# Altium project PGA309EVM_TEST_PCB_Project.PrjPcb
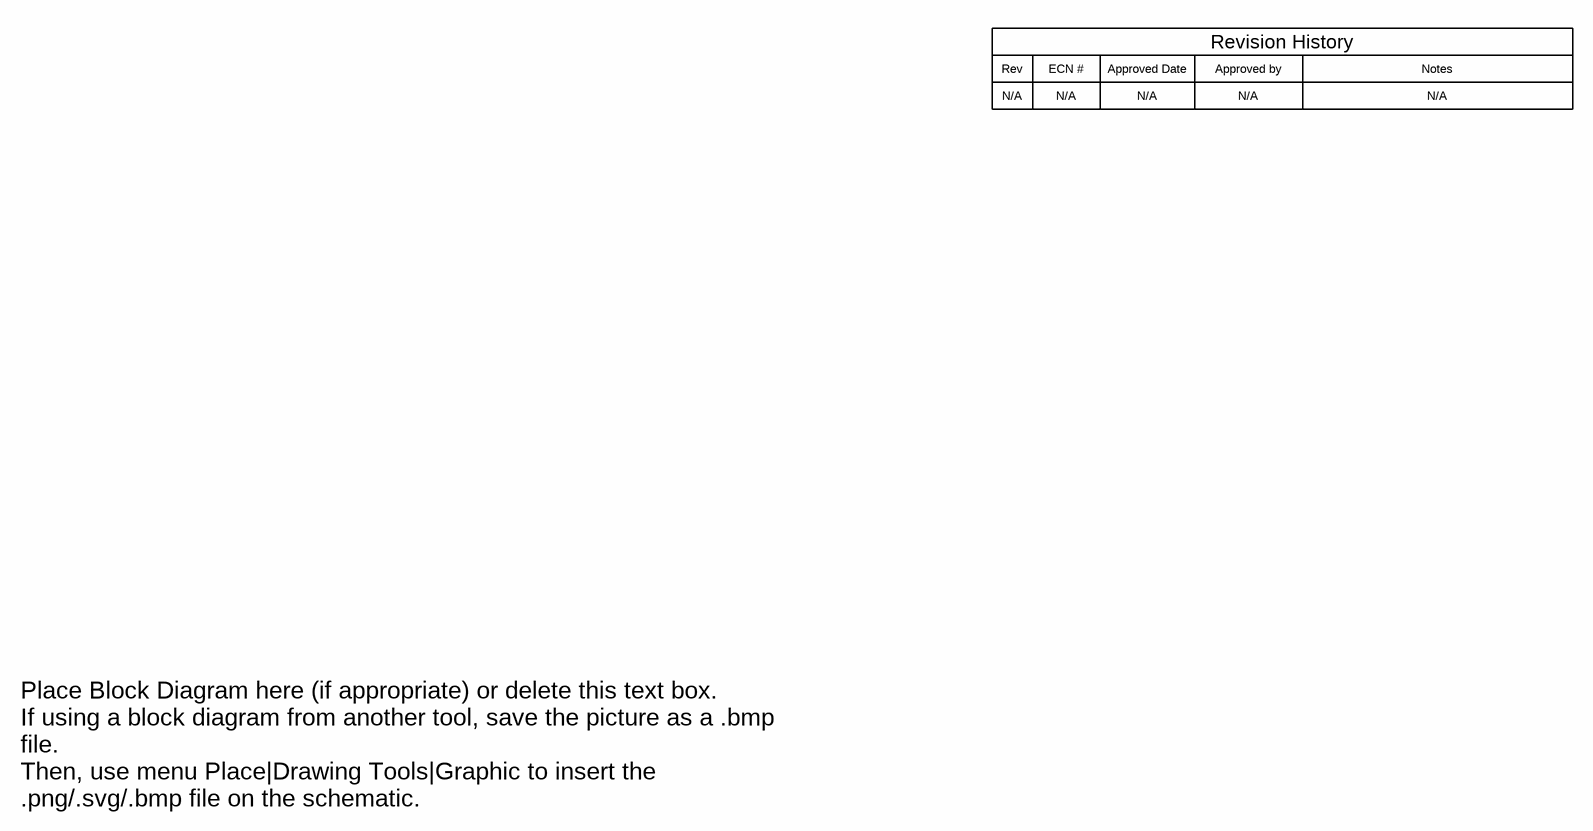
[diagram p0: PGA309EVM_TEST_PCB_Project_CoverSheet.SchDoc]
CopyrightYear: 2016; PCB_Layout: Who did the Layout?; PCB_Rev: E1; PRJ_Customer: Public Release; PRJ_Engineer: Enter name of project lead; PRJ_Number: XX####; PRJ_Title: Change in menu Project|Project Options|Parameters; SCH_Rev: E1; TechSupport: http://www.ti.com/support; TID: N/A
3 sheets, 103 parts. Net scope: global (net labels, ports and power ports of the same name join across sheets).
Board file: PGA309EVM_TEST_PCB_Project_PCB.PcbDoc
Sheets:
  PGA309EVM_TEST_PCB_Project_CoverSheet.SchDoc
  PGA309EVM_TEST_PCB_Project_BlankSheet.SchDoc
  PGA309EVM_TEST_PCB_Project_EVM_Hardware.SchDoc

## Sheet PGA309EVM_TEST_PCB_Project_CoverSheet.SchDoc
size 431 x 279 mm; Date: Not shown in title block; ApprovedBy: Not shown in title block; CheckedBy: Not shown in title block; Author: Not shown in title block; CompanyName: Not shown in title block; Engineer: Not shown in title block; Organization: Not shown in title block; Address1: Not shown in title block; Address2: Not shown in title block; Address3: Not shown in title block; Address4: Not shown in title block; DocumentNumber: 1; Revision: Use project parameter SCH_Rev; SheetNumber: 1; SheetTotal: 3; PageSetup: Record=PageOptions¦CenterHorizontal=True¦CenterVertical=True¦PrintScale=1.00¦XCorrection=1.00¦YCorrection=1.00¦PrintKind=0¦BorderSize=5000000¦LeftOffset=0¦BottomOffset=0¦Orientation=2¦PaperLength=1000¦PaperWidth=1000¦Scale=100¦PaperSource=15¦PrintQuality=600¦MediaType=1¦DitherType=10¦PaperKind=Letter¦PrintScaleMode=1

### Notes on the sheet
- Rev
- N/A
- ECN #
- Approved Date
- Approved by
- Revision History
- Notes
- Place Block Diagram here (if appropriate) or delete this text box.
  If using a block diagram from another tool, save the picture as a .bmp file.
  Then, use menu Place|Drawing Tools|Graphic to insert the .png/.svg/.bmp file on the schematic.

## Sheet PGA309EVM_TEST_PCB_Project_BlankSheet.SchDoc
size 558 x 431 mm; VersionControl_RevNumber: E2; Date: Not shown in title block; ApprovedBy: Not shown in title block; CheckedBy: Not shown in title block; Author: Not shown in title block; CompanyName: Not shown in title block; DrawnBy: Ian Williams; Engineer: Ian Williams; Organization: Not shown in title block; Address1: Not shown in title block; Address2: Not shown in title block; Address3: Not shown in title block; Address4: Not shown in title block; DocumentNumber: 1; Revision: Use project parameter SCH_Rev; SheetNumber: 2; SheetTotal: 3; PageSetup: Record=PageOptions|CenterHorizontal=True|CenterVertical=True|PrintScale=0.49|XCorrection=1.00|YCorrection=1.00|PrintKind=0|BorderSize=5000000|LeftOffset=0|BottomOffset=0|Orientation=2|PaperLength=1000|PaperWidth=1000|Scale=100|PaperSource=15|PrintQuality=600|MediaType=1|DitherType=10|PrintScaleMode=1|PaperKind=Letter (8.5 x 11")|PaperIndex=1
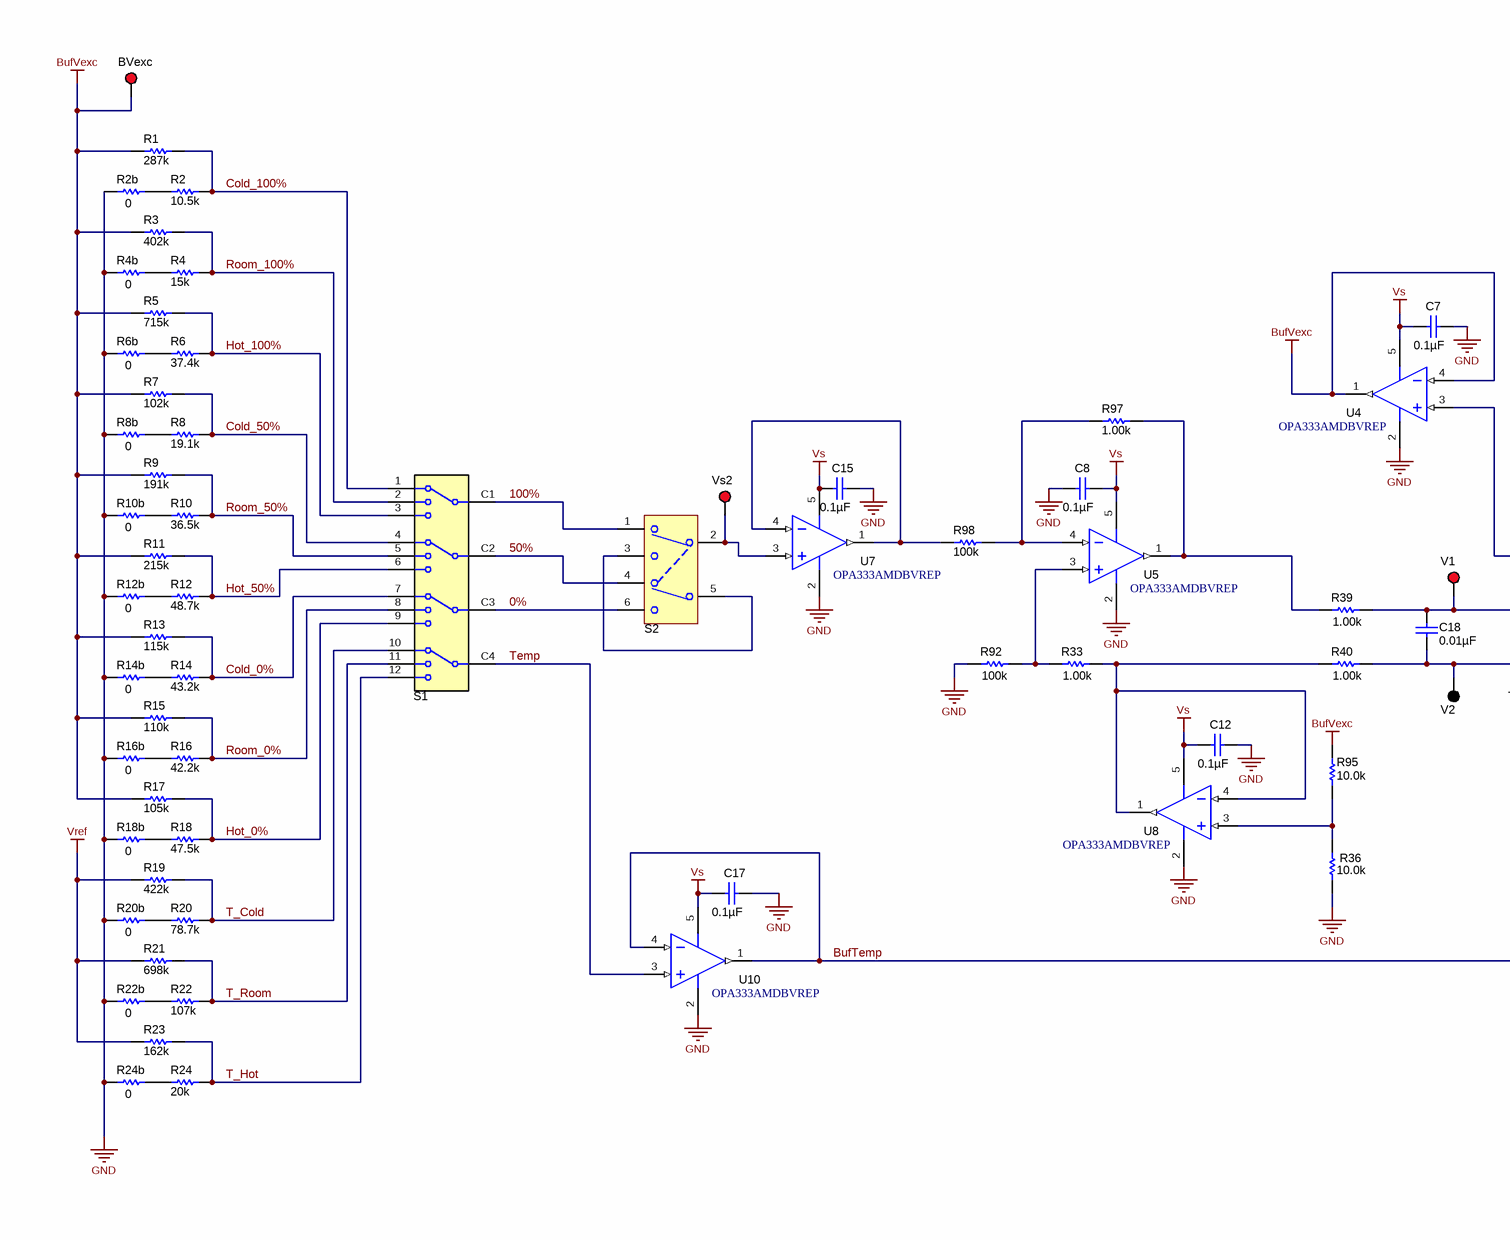
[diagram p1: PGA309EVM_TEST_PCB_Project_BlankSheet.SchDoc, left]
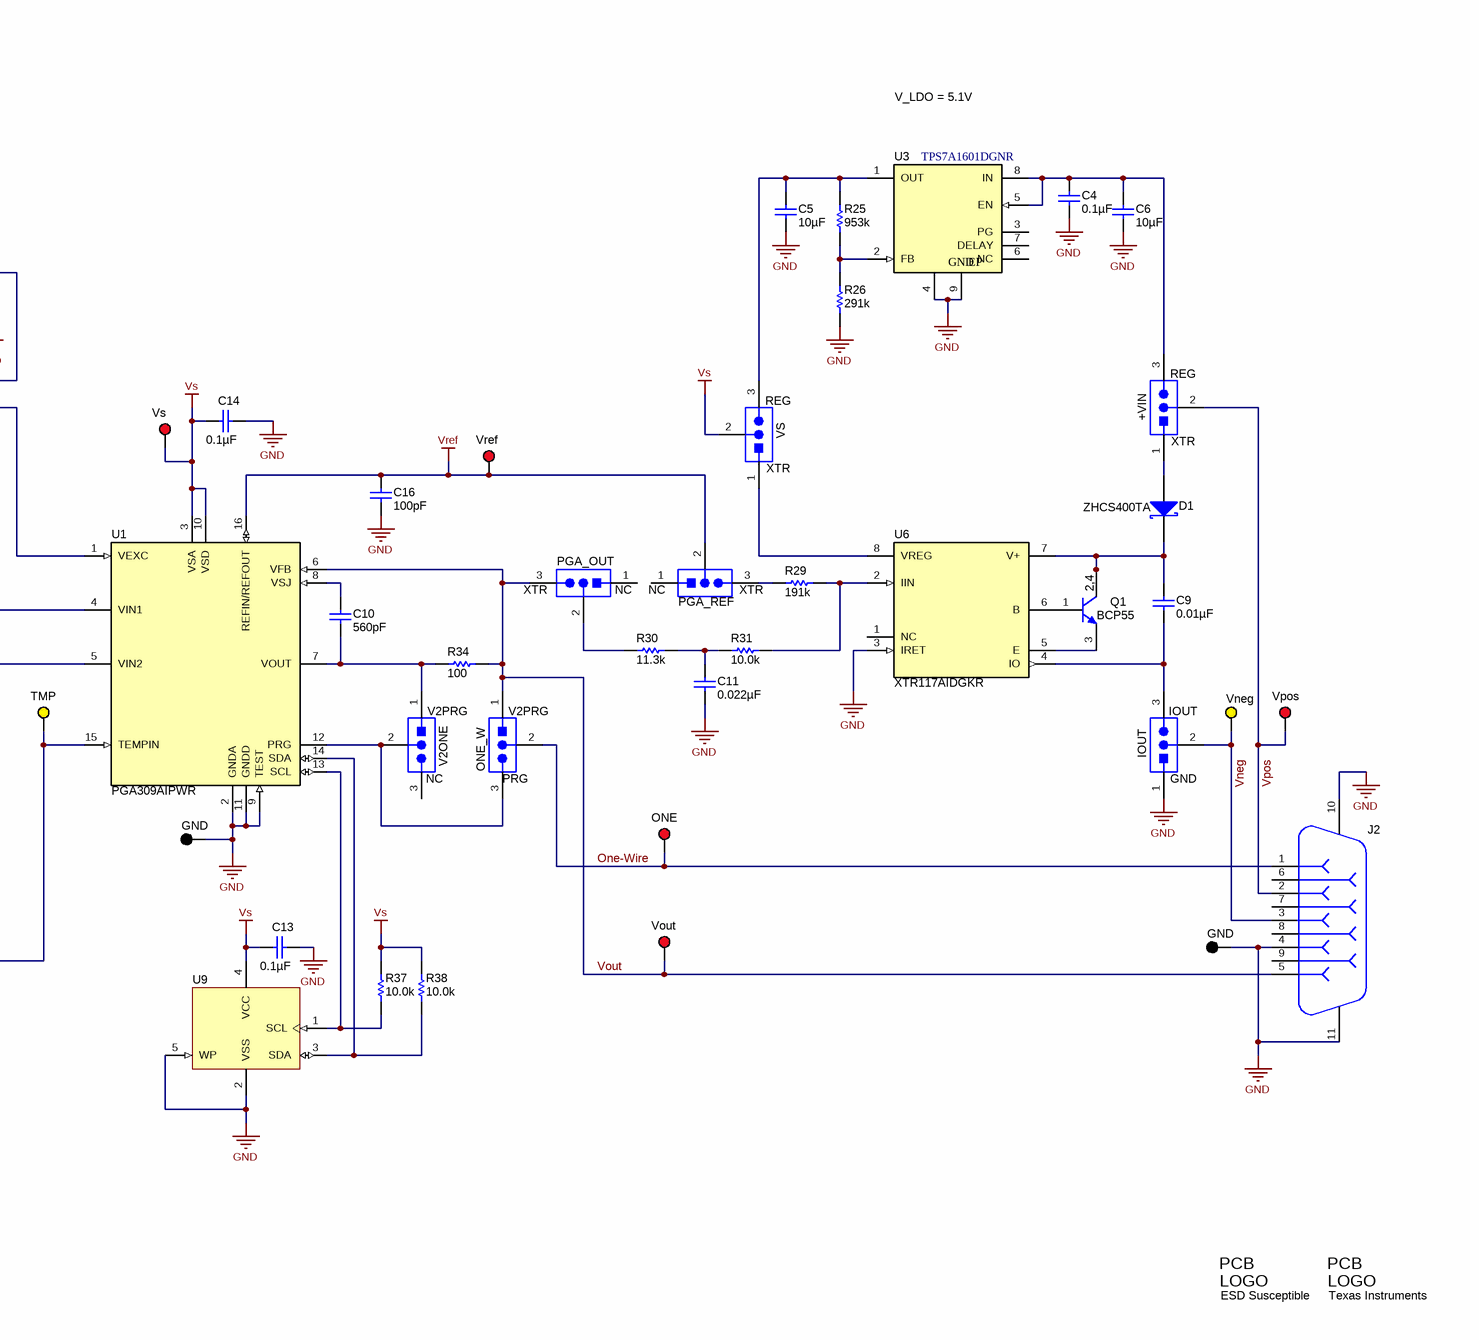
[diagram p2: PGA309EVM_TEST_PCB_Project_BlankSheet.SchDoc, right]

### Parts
(Parts that share a designator on the sheet are numbered #1, #2 ... from top to bottom, then left to right.)
C4  ValueDisplayed: 0.1µF  [0603]  (hidden comment: C0603C104K5RACTU)
C5  ValueDisplayed: 10µF  [1210_280]  (hidden comment: 12103C106KAT2A)
C6  ValueDisplayed: 10µF  [1210_280]  (hidden comment: 12103C106KAT2A)
C7  ValueDisplayed: 0.1µF  [0603]  (hidden comment: C0603C104K5RACTU)
C8  ValueDisplayed: 0.1µF  [0603]  (hidden comment: C0603C104K5RACTU)
C9  ValueDisplayed: 0.01µF  [0603]  (hidden comment: C0603C103J5RACTU)
C10  ValueDisplayed: 560pF  [0603]  (hidden comment: 06035A561JAT2A)
C11  ValueDisplayed: 0.022µF  [0805_HV]  (hidden comment: 08051C223JAT2A)
C12  ValueDisplayed: 0.1µF  [0603]  (hidden comment: C0603C104K5RACTU)
C13  ValueDisplayed: 0.1µF  [0603]  (hidden comment: C0603C104K5RACTU)
C14  ValueDisplayed: 0.1µF  [0603]  (hidden comment: C0603C104K5RACTU)
C15  ValueDisplayed: 0.1µF  [0603]  (hidden comment: C0603C104K5RACTU)
C16  ValueDisplayed: 100pF  [0603]  (hidden comment: 06033C101KAT2A)
C17  ValueDisplayed: 0.1µF  [0603]  (hidden comment: C0603C104K5RACTU)
C18  ValueDisplayed: 0.01µF  [1206]  (hidden comment: C3216C0G1E103J)
D1  ZHCS400TA  [sod-323]
J2  09 65 162 6810  [Harting_09 65 162 6810]  (value not drawn)
JMP1  +VIN  [Mill-Max_800-10-003-10-001000]
JMP2  IOUT  [Mill-Max_800-10-003-10-001000]
JMP3  VS  [Mill-Max_800-10-003-10-001000]
JMP4  PGA_REF  [Mill-Max_800-10-003-10-001000]
JMP5  PGA_OUT  [Mill-Max_800-10-003-10-001000]
JMP6  ONE_W  [Mill-Max_800-10-003-10-001000]
JMP7  V2ONE  [Mill-Max_800-10-003-10-001000]
Logo?#1  ESD Susceptible  [ESD_Overlay_Medium]  (no BOM)
Logo?#2  Texas Instruments  [TI_Stacked_Overlay_Medium]  (no BOM)
Q1  BCP55  [SOT-223]
R1  ValueDisplayed: 287k  [0603]  (hidden comment: CRCW060328K7FKEA)
R2  ValueDisplayed: 10.5k  [0603]  (hidden comment: CRCW06031K05FKEA)
R2b  0  [0603]
R3  ValueDisplayed: 402k  [0603]  (hidden comment: CRCW060340K2FKEA)
R4  ValueDisplayed: 15k  [0603]  (hidden comment: CRCW06031K50FKEA)
R4b  0  [0603]
R5  ValueDisplayed: 715k  [0603]  (hidden comment: CRCW060371K5FKEA)
R6  ValueDisplayed: 37.4k  [0603]  (hidden comment: CRCW06033K74FKEA)
R6b  0  [0603]
R7  ValueDisplayed: 102k  [0603]  (hidden comment: CRCW060310K2FKEA)
R8  ValueDisplayed: 19.1k  [0603]  (hidden comment: CRCW06031K91FKEA)
R8b  0  [0603]
R9  ValueDisplayed: 191k  [0603]  (hidden comment: RT0603BRD0719K3L)
R10  ValueDisplayed: 36.5k  [0603]  (hidden comment: CRCW06033K65FKEA)
R10b  0  [0603]
R11  ValueDisplayed: 215k  [0603]  (hidden comment: CRCW060321K5FKEA)
R12  ValueDisplayed: 48.7k  [0603]  (hidden comment: CRCW06034K87FKEA)
R12b  0  [0603]
R13  ValueDisplayed: 115k  [0603]  (hidden comment: CRCW060311K5FKEA)
R14  ValueDisplayed: 43.2k  [0603]  (hidden comment: RT0603BRD074K37L)
R14b  0  [0603]
R15  ValueDisplayed: 110k  [0603]  (hidden comment: CRCW060311K0FKEA)
R16  ValueDisplayed: 42.2k  [0603]  (hidden comment: CRCW06034K22FKEA)
R16b  0  [0603]
R17  ValueDisplayed: 105k  [0603]  (hidden comment: CRCW06031K05FKEA)
R18  ValueDisplayed: 47.5k  [0603]  (hidden comment: RT0603BRD0723K4L)
R18b  0  [0603]
R19  ValueDisplayed: 422k  [0603]  (hidden comment: CRCW060342K2FKEA)
R20  ValueDisplayed: 78.7k  [0603]  (hidden comment: RT0603BRD077K96L)
R20b  0  [0603]
R21  ValueDisplayed: 698k  [0603]  (hidden comment: RT0603BRD076K9L)
R22  ValueDisplayed: 107k  [0603]  (hidden comment: CRCW06031K07FKEA)
R22b  0  [0603]
R23  ValueDisplayed: 162k  [0603]  (hidden comment: CRCW060316K2FKEA)
R24  ValueDisplayed: 20k  [0603]  (hidden comment: CPF0603B2K0E)
R24b  0  [0603]
R25  ValueDisplayed: 953k  [0603]  (hidden comment: CRCW0603953KFKEA)
R26  ValueDisplayed: 291k  [0603]  (hidden comment: RT0603BRD07291KL)
R29  ValueDisplayed: 191k  [0603]  (hidden comment: CRCW0603191KFKEA)
R30  ValueDisplayed: 11.3k  [0603]  (hidden comment: CRCW060311K3FKEA)
R31  ValueDisplayed: 10.0k  [0603]  (hidden comment: CRCW060310K0FKEA)
R33  ValueDisplayed: 1.00k  [0603]  (hidden comment: CRCW06031K00FKEA)
R34  ValueDisplayed: 100  [0603]  (hidden comment: CRCW0603100RFKEA)
R36  ValueDisplayed: 10.0k  [0603]  (hidden comment: CRCW060310K0FKEA)
R37  ValueDisplayed: 10.0k  [0603]  (hidden comment: CRCW060310K0FKEA)
R38  ValueDisplayed: 10.0k  [0603]  (hidden comment: CRCW060310K0FKEA)
R39  ValueDisplayed: 1.00k  [0603]  (hidden comment: CRCW06031K00FKEA)
R40  ValueDisplayed: 1.00k  [0603]  (hidden comment: CRCW06031K00FKEA)
R92  ValueDisplayed: 100k  [0603]  (hidden comment: RT0603BRD07100KL)
R95  ValueDisplayed: 10.0k  [0603]  (hidden comment: CRCW060310K0FKEA)
R97  ValueDisplayed: 1.00k  [0603]  (hidden comment: CRCW06031K00FKEA)
R98  ValueDisplayed: 100k  [0603]  (hidden comment: RT0603BRD07100KL)
S1  56P30-01-4-03N  [SW_56P30-01-4-03N]  (value not drawn)
S2  M2024SS1G03  [SW_M2024]  (value not drawn)
TP2  BVexc  [Keystone5000]
TP3  Vs  [Keystone5000]
TP4  Vref  [Keystone5000]
TP5  V1  [Keystone5000]
TP6  TMP  [Keystone5004]
TP7  Vneg  [Keystone5004]
TP8  Vpos  [Keystone5000]
TP9  V2  [Keystone5006]
TP10  ONE  [Keystone5000]
TP11  GND  [Keystone5006]
TP12  Vout  [Keystone5000]
TP13  GND  [Keystone5006]
TP14  Vs2  [Keystone5000]
U1  PGA309AIPWR  [PW0016A_N]
U3  TPS7A1601DGNR  [DGN0008C_N]
U4  OPA333AMDBVREP  [DBV0005A_N]
U5  OPA333AMDBVREP  [DBV0005A_N]
U6  XTR117AIDGKR  [DGK0008A_N]
U7  OPA333AMDBVREP  [DBV0005A_N]
U8  OPA333AMDBVREP  [DBV0005A_N]
U9  24LC32AT-I/OT  [SOT-23-5]  (value not drawn)
U10  OPA333AMDBVREP  [DBV0005A_N]

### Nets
BufVexc: R1.1 R3.1 R5.1 R7.1 R9.1 R11.1 R13.1 R15.1 R17.1 R95.2 TP2.1 U4.1(OUT) U4.4(IN-)
GND: C4.2 C5.2 C6.2 C7.1 C8.2 C11.2 C12.1 C13.1 C14.1 C15.1 C16.2 C17.1 J2.4 J2.10 J2.11 JMP2.1 R2b.1 R4b.1 R6b.1 R8b.1 R10b.1 R12b.1 R14b.1 R16b.1 R18b.1 R20b.1 R22b.1 R24b.1 R26.1 R36.1 R92.2 TP11.1 TP13.1 U1.2(GNDA) U1.9(TEST) U1.11(GNDD) U3.4(GND) U3.9(EP) U4.2(V-) U5.2(V-) U6.3(IRET) U7.2(V-) U8.2(V-) U9.2(VSS) U9.5(WP) U10.2(V-)
Vref: C16.1 JMP4.2 R19.1 R21.1 R23.1 TP4.1 U1.16(REFIN/REFOUT)
Vs: C7.2 C8.1 C12.2 C13.2 C14.2 C15.2 C17.2 JMP3.2 R37.2 R38.2 TP3.1 U1.3(VSA) U1.10(VSD) U4.5(V+) U5.5(V+) U7.5(V+) U8.5(V+) U9.4(VCC) U10.5(V+)
0%: S1.C3 S2.6(OUT)
50%: S1.C2 S2.4(OUT)
100%: S1.C1 S2.1(OUT)
BufTemp: TP6.1 U1.15(TEMPIN) U10.1(OUT) U10.4(IN-)
Cold_0%: R13.2 R14.2 S1.7
Cold_50%: R7.2 R8.2 S1.4
Cold_100%: R1.2 R2.2 S1.1
Hot_0%: R17.2 R18.2 S1.9
Hot_50%: R11.2 R12.2 S1.6
Hot_100%: R5.2 R6.2 S1.3
One-Wire: J2.1 JMP6.2 TP10.1
Room_0%: R15.2 R16.2 S1.8
Room_50%: R9.2 R10.2 S1.5
Room_100%: R3.2 R4.2 S1.2
T_Cold: R19.2 R20.2 S1.10
T_Hot: R23.2 R24.2 S1.12
T_Room: R21.2 R22.2 S1.11
Temp: S1.C4 U10.3(IN+)
Vneg: J2.3 JMP2.2 TP7.1
Vout: J2.5 JMP5.3 JMP6.1 R34.2 TP12.1 U1.6(VFB)
Vpos: J2.2 JMP1.2 TP8.1
NetC4_1: C4.1 C6.1 JMP1.3 U3.5(EN) U3.8(IN)
NetC5_1: C5.1 JMP3.3 R25.2 U3.1(OUT)
NetC9_1: C9.1 D1.1(K) Q1.2(C) Q1.4(C) U6.7(V+)
NetC9_2: C9.2 JMP2.3 U6.4(IO)
NetC10_1: C10.1 U1.8(VSJ)
NetC10_2: C10.2 JMP7.1 R34.1 U1.7(VOUT)
NetC11_1: C11.1 R30.2 R31.2
NetC18_1: C18.1 R39.2 TP5.1 U1.4(VIN1)
NetC18_2: C18.2 R40.2 TP9.1 U1.5(VIN2)
NetD1_2: D1.2(A) JMP1.1
NetJMP3_1: JMP3.1 U6.8(VREG)
NetJMP4_3: JMP4.3 R29.1
NetJMP5_2: JMP5.2 R30.1
NetJMP6_3: JMP6.3 JMP7.2 U1.12(PRG)
NetQ1_1: Q1.1(B) U6.6(B)
NetQ1_3: Q1.3(E) U6.5(E)
NetR2_1: R2.1 R2b.2
NetR4_1: R4.1 R4b.2
NetR6_1: R6.1 R6b.2
NetR8_1: R8.1 R8b.2
NetR10_1: R10.1 R10b.2
NetR12_1: R12.1 R12b.2
NetR14_1: R14.1 R14b.2
NetR16_1: R16.1 R16b.2
NetR18_1: R18.1 R18b.2
NetR20_1: R20.1 R20b.2
NetR22_1: R22.1 R22b.2
NetR24_1: R24.1 R24b.2
NetR25_1: R25.1 R26.2 U3.2(FB)
NetR29_2: R29.2 R31.1 U6.2(IIN)
NetR33_1: R33.1 R92.1 U5.3(IN+)
NetR33_2: R33.2 R40.1 U8.1(OUT) U8.4(IN-)
NetR36_2: R36.2 R95.1 U8.3(IN+)
NetR37_1: R37.1 U1.13(SCL) U9.1(SCL)
NetR38_1: R38.1 U1.14(SDA) U9.3(SDA)
NetR39_1: R39.1 R97.2 U5.1(OUT)
NetR97_1: R97.1 R98.1 U5.4(IN-)
NetR98_2: R98.2 U7.1(OUT) U7.4(IN-)
NetS2_2: S2.2(COM) TP14.1 U7.3(IN+)
NetS2_3: S2.3(OUT) S2.5(COM)
NetU1_1: U1.1(VEXC) U4.3(IN+)

Not connected (* = marked no-connect by the designer): J2 6 7 8 9; JMP4 1; JMP5 1; JMP7 3; U3 3(PG) 6(NC) 7(DELAY); U6 1(NC)

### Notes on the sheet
- V_LDO = 5.1V
- (near JMP1) REG
- (near JMP3) REG
- (near JMP1) XTR
- (near JMP3) XTR
- (near JMP5) XTR
- (near JMP5) NC
- (near JMP4) NC
- (near JMP4) XTR
- (near JMP7) V2PRG
- (near JMP6) V2PRG
- (near JMP2) IOUT
- (near JMP7) NC
- (near JMP6) PRG
- (near JMP2) GND

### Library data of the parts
C4 C7 C8 C12-C15 C17 = C0603C104K5RACTU: CAP, CERM, 0.1 µF, 50 V, +/- 10%, X7R, 0603; Manufacturer: Kemet; Polarized: N; CompType: Capacitor; Value: 0.1uF; U/M: EA; Cap_F: 0.0000001; Tolerance_%: 10; Value1: Unknown; VDC_V: 50; Value2: 50V; TaMin_C: -55; TaMax_C: 125; AEC Category: Q200
C5 C6 = 12103C106KAT2A: CAP, CERM, 10 µF, 25 V, +/- 10%, X7R, 1210; Manufacturer: AVX; Polarized: N; CompType: Capacitor; Value: 10uF; U/M: EA; Cap_F: 0.00001; Tolerance_%: 10; Value1: Unknown; VDC_V: 25; Value2: 25V; TaMin_C: -55; TaMax_C: 125; Cap_Case: 1210; AEC Category: Q200
C9 = C0603C103J5RACTU: CAP, CERM, 0.01 µF, 50 V, +/- 5%, X7R, 0603; Manufacturer: Kemet; Polarized: N; CompType: Capacitor; Value: 0.01uF; U/M: EA; Cap_F: 0.00000001; Tolerance_%: 5; Value1: Unknown; VDC_V: 50; Value2: 50V; TaMin_C: -55; TaMax_C: 125; AEC Category: Q200
C10 = 06035A561JAT2A: CAP, CERM, 560 pF, 50 V, +/- 5%, C0G/NP0, 0603; Manufacturer: AVX; Polarized: N; CompType: Capacitor; Value: 560pF; U/M: EA; Cap_F: 0.00000000056; Tolerance_%: 5; ESR_ohm: 0.059; Value1: 0.059 ohm; VDC_V: 50; Value2: 50V; TaMin_C: -55; TaMax_C: 125; AEC Category: Q200
C11 = 08051C223JAT2A: CAP, CERM, 0.022 µF, 100 V, +/- 5%, X7R, 0805; Manufacturer: AVX; Polarized: N; CompType: Capacitor; Value: 0.022uF; U/M: EA; Cap_F: 0.000000022; Tolerance_%: 5; ESR_ohm: 0.052; Value1: 0.052 ohm; VDC_V: 100; Value2: 100V; TaMin_C: -55; TaMax_C: 125; Cap_Case: 0805; AEC Category: Q200
C16 = 06033C101KAT2A: CAP, CERM, 100 pF, 25 V, +/- 10%, X7R, 0603; Manufacturer: AVX; Polarized: N; CompType: Capacitor; Value: 100pF; U/M: EA; Cap_F: 0.0000000001; Tolerance_%: 10; Value1: Unknown; VDC_V: 25; Value2: 25V; TaMin_C: -55; TaMax_C: 125; AEC Category: Q200
C18 = C3216C0G1E103J: CAP, CERM, 0.01 µF, 25 V, +/- 5%, C0G/NP0, 1206; Manufacturer: TDK; Polarized: N; CompType: Capacitor; Value: 0.01uF; U/M: EA; Cap_F: 0.00000001; Tolerance_%: 5; ESR_ohm: 0.0275; Value1: 0.0275 ohm; VDC_V: 25; Value2: 25V; TaMin_C: -55; TaMax_C: 125; AEC Category: Q200
D1 = ZHCS400TA: Diode, Schottky, 40 V, 0.4 A, SOD-323; Manufacturer: Diodes Inc.; U/M: EA; Vf_V: 0.4; Value: 40V; Value1: 0.4A; Value2: 0.4V; Vr_V: 40; AEC Category: Q101
J2 = 09 65 162 6810: D-Sub-9, 11Pos, Male, TH; Manufacturer: Harting; SymbolCreator: x0208326; CompType: D-Sub; U/M: EA
JMP1-JMP7 = 800-10-003-10-001000: Header, 100mil, 3x1, TH; Manufacturer: Mill-Max; SymbolCreator: a0799628
Logo?#1 = ESD_Susceptible: ESD Susceptible Symbol; SymbolCreator: a0412235
Logo?#2 = TI_Logo: Texas Instrument Corporate Signature; SymbolCreator: a0412235
Q1 = BCP55, Fairchild Semiconductor: Transistor, NPN, 60 V, 1.5 A, SOT-223; SymbolCreator: a0412235; PNP: 0; NPN: 1; Vceo_V: 60; Vcesat1_V: 0.5; Value: 60 V; IcRated_A: 1.5; Value1: 1.5 A; HfeMax: 250; TaMin_C: -55; TaMax_C: 150; CompType: BJT; U/M: EA; AEC Category: Q101
R1 = CRCW060328K7FKEA: RES, 28.7 k, 1%, 0.1 W, 0603; Manufacturer: Vishay-Dale; CompType: Resistor; Value: 28.7k; Res_ohm: 28700; Value_Code: 28k7; Tolerance_%: 1; Power_W: 0.1; Value2: 0.1W; VDC_V: 75; TempCo: 100 ppm/C; EIA_Code: E96; U/M: EA; AEC Category: Q200
R2 R17 = CRCW06031K05FKEA: RES, 1.05 k, 1%, 0.1 W, 0603; Manufacturer: Vishay-Dale; CompType: Resistor; Value: 1.05k; Res_ohm: 1050; Value_Code: 1k05; Tolerance_%: 1; Power_W: 0.1; Value2: 0.1W; VDC_V: 75; TempCo: 100 ppm/C; EIA_Code: E96; U/M: EA; AEC Category: Q200
R2b R4b R6b R8b R10b R12b R14b R16b R18b R20b R22b R24b = Resistor: RES, xxx ohm, x%, xW, [PackageReference]; Manufacturer: Used in BOM report; U/M: EA
R3 = CRCW060340K2FKEA: RES, 40.2 k, 1%, 0.1 W, 0603; Manufacturer: Vishay-Dale; CompType: Resistor; Value: 40.2k; Res_ohm: 40200; Value_Code: 40k2; Tolerance_%: 1; Power_W: 0.1; Value2: 0.1W; VDC_V: 75; TempCo: 100 ppm/C; EIA_Code: E96; U/M: EA; AEC Category: Q200
R4 = CRCW06031K50FKEA: RES, 1.50 k, 1%, 0.1 W, 0603; Manufacturer: Vishay-Dale; CompType: Resistor; Value: 1.50k; Res_ohm: 1500; Value_Code: 1k50; Tolerance_%: 1; Power_W: 0.1; Value2: 0.1W; VDC_V: 75; TempCo: 100 ppm/C; EIA_Code: E96; U/M: EA; AEC Category: Q200
R5 = CRCW060371K5FKEA: RES, 71.5 k, 1%, 0.1 W, 0603; Manufacturer: Vishay-Dale; CompType: Resistor; Value: 71.5k; Res_ohm: 71500; Value_Code: 71k5; Tolerance_%: 1; Power_W: 0.1; Value2: 0.1W; VDC_V: 75; TempCo: 100 ppm/C; EIA_Code: E96; U/M: EA; AEC Category: Q200
R6 = CRCW06033K74FKEA: RES, 3.74 k, 1%, 0.1 W, 0603; Manufacturer: Vishay-Dale; CompType: Resistor; Value: 3.74k; Res_ohm: 3740; Value_Code: 3k74; Tolerance_%: 1; Power_W: 0.1; Value2: 0.1W; VDC_V: 75; TempCo: 100 ppm/C; EIA_Code: E96; U/M: EA; AEC Category: Q200
R7 = CRCW060310K2FKEA: RES, 10.2 k, 1%, 0.1 W, 0603; Manufacturer: Vishay-Dale; CompType: Resistor; Value: 10.2k; Res_ohm: 10200; Value_Code: 10k2; Tolerance_%: 1; Power_W: 0.1; Value2: 0.1W; VDC_V: 75; TempCo: 100 ppm/C; EIA_Code: E96; U/M: EA; AEC Category: Q200
R8 = CRCW06031K91FKEA: RES, 1.91 k, 1%, 0.1 W, 0603; Manufacturer: Vishay-Dale; CompType: Resistor; Value: 1.91k; Res_ohm: 1910; Value_Code: 1k91; Tolerance_%: 1; Power_W: 0.1; Value2: 0.1W; VDC_V: 75; TempCo: 100 ppm/C; EIA_Code: E96; U/M: EA; AEC Category: Q200
R9 = RT0603BRD0719K3L: RES, 19.3 k, 0.1%, 0.1 W, 0603; Manufacturer: Yageo America; CompType: Resistor; Value: 19.3k; Res_ohm: 19300; Value_Code: 19k3; Tolerance_%: 0.1; Value2: 0.1W; VDC_V: 75; TempCo: 25 ppm/C; EIA_Code: E192; U/M: EA; AEC Category: Q200
R10 = CRCW06033K65FKEA: RES, 3.65 k, 1%, 0.1 W, 0603; Manufacturer: Vishay-Dale; CompType: Resistor; Value: 3.65k; Res_ohm: 3650; Value_Code: 3k65; Tolerance_%: 1; Power_W: 0.1; Value2: 0.1W; VDC_V: 75; TempCo: 100 ppm/C; EIA_Code: E96; U/M: EA; AEC Category: Q200
R11 = CRCW060321K5FKEA: RES, 21.5 k, 1%, 0.1 W, 0603; Manufacturer: Vishay-Dale; CompType: Resistor; Value: 21.5k; Res_ohm: 21500; Value_Code: 21k5; Tolerance_%: 1; Power_W: 0.1; Value2: 0.1W; VDC_V: 75; TempCo: 100 ppm/C; EIA_Code: E96; U/M: EA; AEC Category: Q200
R12 = CRCW06034K87FKEA: RES, 4.87 k, 1%, 0.1 W, 0603; Manufacturer: Vishay-Dale; CompType: Resistor; Value: 4.87k; Res_ohm: 4870; Value_Code: 4k87; Tolerance_%: 1; Power_W: 0.1; Value2: 0.1W; VDC_V: 75; TempCo: 100 ppm/C; EIA_Code: E96; U/M: EA; AEC Category: Q200
R13 = CRCW060311K5FKEA: RES, 11.5 k, 1%, 0.1 W, 0603; Manufacturer: Vishay-Dale; CompType: Resistor; Value: 11.5k; Res_ohm: 11500; Value_Code: 11k5; Tolerance_%: 1; Power_W: 0.1; Value2: 0.1W; VDC_V: 75; TempCo: 100 ppm/C; EIA_Code: E96; U/M: EA; AEC Category: Q200
R14 = RT0603BRD074K37L: RES, 4.37 k, 0.1%, 0.1 W, 0603; Manufacturer: Yageo America; CompType: Resistor; Value: 4.37k; Res_ohm: 4370; Value_Code: 4k37; Tolerance_%: 0.1; Value2: 0.1W; VDC_V: 75; TempCo: 25 ppm/C; EIA_Code: E192; U/M: EA; AEC Category: Q200
R15 = CRCW060311K0FKEA: RES, 11.0 k, 1%, 0.1 W, 0603; Manufacturer: Vishay-Dale; CompType: Resistor; Value: 11.0k; Res_ohm: 11000; Value_Code: 11k0; Tolerance_%: 1; Power_W: 0.1; Value2: 0.1W; VDC_V: 75; TempCo: 100 ppm/C; EIA_Code: E96; U/M: EA; AEC Category: Q200
R16 = CRCW06034K22FKEA: RES, 4.22 k, 1%, 0.1 W, 0603; Manufacturer: Vishay-Dale; CompType: Resistor; Value: 4.22k; Res_ohm: 4220; Value_Code: 4k22; Tolerance_%: 1; Power_W: 0.1; Value2: 0.1W; VDC_V: 75; TempCo: 100 ppm/C; EIA_Code: E96; U/M: EA; AEC Category: Q200
R18 = RT0603BRD0723K4L: RES, 23.4 k, 0.1%, 0.1 W, 0603; Manufacturer: Yageo America; CompType: Resistor; Value: 23.4k; Res_ohm: 23400; Value_Code: 23k4; Tolerance_%: 0.1; Value2: 0.1W; VDC_V: 75; TempCo: 25 ppm/C; EIA_Code: E192; U/M: EA; AEC Category: Q200
R19 = CRCW060342K2FKEA: RES, 42.2 k, 1%, 0.1 W, 0603; Manufacturer: Vishay-Dale; CompType: Resistor; Value: 42.2k; Res_ohm: 42200; Value_Code: 42k2; Tolerance_%: 1; Power_W: 0.1; Value2: 0.1W; VDC_V: 75; TempCo: 100 ppm/C; EIA_Code: E96; U/M: EA; AEC Category: Q200
R20 = RT0603BRD077K96L: RES, 7.96 k, 0.1%, 0.1 W, 0603; Manufacturer: Yageo America; CompType: Resistor; Value: 7.96k; Res_ohm: 7960; Value_Code: 7k96; Tolerance_%: 0.1; Value2: 0.1W; VDC_V: 75; TempCo: 25 ppm/C; EIA_Code: E192; U/M: EA; AEC Category: Q200
R21 = RT0603BRD076K9L: RES, 6.90 k, 0.1%, 0.1 W, 0603; Manufacturer: Yageo America; CompType: Resistor; Value: 6.90k; Res_ohm: 6900; Value_Code: 6k90; Tolerance_%: 0.1; Value2: 0.1W; VDC_V: 75; TempCo: 25 ppm/C; EIA_Code: E192; U/M: EA; AEC Category: Q200
R22 = CRCW06031K07FKEA: RES, 1.07 k, 1%, 0.1 W, 0603; Manufacturer: Vishay-Dale; CompType: Resistor; Value: 1.07k; Res_ohm: 1070; Value_Code: 1k07; Tolerance_%: 1; Power_W: 0.1; Value2: 0.1W; VDC_V: 75; TempCo: 100 ppm/C; EIA_Code: E96; U/M: EA; AEC Category: Q200
R23 = CRCW060316K2FKEA: RES, 16.2 k, 1%, 0.1 W, 0603; Manufacturer: Vishay-Dale; CompType: Resistor; Value: 16.2k; Res_ohm: 16200; Value_Code: 16k2; Tolerance_%: 1; Power_W: 0.1; Value2: 0.1W; VDC_V: 75; TempCo: 100 ppm/C; EIA_Code: E96; U/M: EA; AEC Category: Q200
R24 = CPF0603B2K0E: RES, 2.00 k, 0.1%, 0.063 W, 0603; Manufacturer: TE Connectivity; CompType: Resistor; Value: 2.00k; Res_ohm: 2000; Value_Code: 2k00; Tolerance_%: 0.1; Power_W: 0.063; Value2: 0.063W; VDC_V: 50; TempCo: 25 ppm/C; EIA_Code: E192; U/M: EA; AEC Category: Q200
R25 = CRCW0603953KFKEA: RES, 953 k, 1%, 0.1 W, 0603; Manufacturer: Vishay-Dale; CompType: Resistor; Value: 953k; Res_ohm: 953000; Tolerance_%: 1; Power_W: 0.1; Value2: 0.1W; VDC_V: 75; TempCo: 100 ppm/C; EIA_Code: E96; U/M: EA; AEC Category: Q200
R26 = RT0603BRD07291KL: RES, 291 k, 0.1%, 0.1 W, 0603; Manufacturer: Yageo America; CompType: Resistor; Value: 291k; Res_ohm: 291000; Tolerance_%: 0.1; Value2: 0.1W; VDC_V: 75; TempCo: 25 ppm/C; EIA_Code: E192; U/M: EA; AEC Category: Q200
R29 = CRCW0603191KFKEA: RES, 191 k, 1%, 0.1 W, 0603; Manufacturer: Vishay-Dale; CompType: Resistor; Value: 191k; Res_ohm: 191000; Tolerance_%: 1; Power_W: 0.1; Value2: 0.1W; VDC_V: 75; TempCo: 100 ppm/C; EIA_Code: E96; U/M: EA; AEC Category: Q200
R30 = CRCW060311K3FKEA: RES, 11.3 k, 1%, 0.1 W, 0603; Manufacturer: Vishay-Dale; CompType: Resistor; Value: 11.3k; Res_ohm: 11300; Value_Code: 11k3; Tolerance_%: 1; Power_W: 0.1; Value2: 0.1W; VDC_V: 75; TempCo: 100 ppm/C; EIA_Code: E96; U/M: EA; AEC Category: Q200
R31 R36-R38 R95 = CRCW060310K0FKEA: RES, 10.0 k, 1%, 0.1 W, 0603; Manufacturer: Vishay-Dale; CompType: Resistor; Value: 10.0k; Res_ohm: 10000; Value_Code: 10k0; Tolerance_%: 1; Power_W: 0.1; Value2: 0.1W; VDC_V: 75; TempCo: 100 ppm/C; EIA_Code: E96; U/M: EA; AEC Category: Q200
R33 R39 R40 R97 = CRCW06031K00FKEA: RES, 1.00 k, 1%, 0.1 W, 0603; Manufacturer: Vishay-Dale; CompType: Resistor; Value: 1.00k; Res_ohm: 1000; Value_Code: 1k00; Tolerance_%: 1; Power_W: 0.1; Value2: 0.1W; VDC_V: 75; TempCo: 100 ppm/C; EIA_Code: E96; U/M: EA; AEC Category: Q200
R34 = CRCW0603100RFKEA: RES, 100, 1%, 0.1 W, 0603; Manufacturer: Vishay-Dale; CompType: Resistor; Value: 100; Value_Code: 100R; Tolerance_%: 1; Power_W: 0.1; Value2: 0.1W; VDC_V: 75; TempCo: 100 ppm/C; EIA_Code: E96; U/M: EA; AEC Category: Q200
R92 R98 = RT0603BRD07100KL: RES, 100 k, 0.1%, 0.1 W, 0603; Manufacturer: Yageo America; CompType: Resistor; Value: 100k; Res_ohm: 100000; Tolerance_%: 0.1; Value2: 0.1W; VDC_V: 75; TempCo: 25 ppm/C; EIA_Code: E192; U/M: EA; AEC Category: Q200
S1 = 56P30-01-4-03N: Switch, 4P3T, 4Pole, 3 Pos, 0.2 A, 115 VAC, 30 VDC, TH; Manufacturer: Grayhill; SymbolCreator: Altium; VDC_V: 30; PositionCount: 3; CurrentRating_mA: 200
S2 = M2024SS1G03: Switch, Toggle SP3T, 0.4VA, 28V, TH; Manufacturer: NKK Switches; SymbolCreator: Altium; VDC_V: 28; SwitchFunction: On-On-On; PositionCount: 3; CurrentRating_mA: 100
TP2-TP5 TP8 TP10 TP12 TP14 = 5000: Test Point, Miniature, Red, TH; Manufacturer: Keystone; CompType: Test Point Loop; ContactFinish: Silver
TP6 TP7 = 5004: Test Point, Miniature, Yellow, TH; Manufacturer: Keystone; CompType: Test Point Loop; ContactFinish: Silver
TP9 TP11 TP13 = 5006: Test Point, Compact, Black, TH; Manufacturer: Keystone; CompType: Test Point Loop; ContactFinish: Silver
U1 = PGA309AIPWR: Voltage Output Programmable Sensor Conditioner, PW0016A; Alternate PartNumber: PGA309AIPWT; Manufacturer: Texas Instruments; SymbolCreator: Altium; CompType: IC; U/M: EA
U3 = TPS7A1601DGNR: Single Output LDO, 100 mA, Adjustable 1.2 to 18.5 V Output, 3 to 60 V Input, with Enable and Power Good, 8-pin MSOP (DGN), -40 to 125 degC, Green (RoHS & no Sb/Br); Manufacturer: Texas Instruments; Alternate PartNumber: Equivalent; Accuracy(%): 2; Iout(Max)(A): 0.1; Iq(Typ)(mA): 0.004; Power Good: TRUE; Rating: Catalog; SubFamily: Single Channel LDO; Vdo(Typ)(mV): 60; Vin(Min)(V): 3; Vout Adj(Max)(V): 18.5; Vout Adj(Min)(V): 1.2
U4 U5 U7 U8 U10 = OPA333AMDBVREP: Enhanced Product, Micropower CMOS Operational Amplifier Zero-Drift Series, 1.8 to 5.5 V, -55 to 125 degC, 5-pin SOT23 (DBV0005A), Green (RoHS & no Sb/Br); Alternate Manufacturer: Texas Instruments; Alternate PartNumber: Equivalent; CMRR(Min)(dB): 102; GBW(Typ)(MHz): 0.35; Iq per channel(Max)(mA): 0.025; Slew Rate(Typ)(V/us): 0.16; Sub Family: General Purpose Amplifier; Total Supply Voltage(Max)(+5V is 5, +/-5V is 10): 5.5; Total Supply Voltage(Min)(+5V is 5, +/-5V is 10): 1.8
U6 = XTR117AIDGKR: 4-20mA Current-Loop Transmitter, DGK0008A; Alternate PartNumber: XTR117AIDGKT; Manufacturer: Texas Instruments; SymbolCreator: Altium; CompType: IC; U/M: EA
U9 = 24LC32AT-I/OT: 32K I2C™ Serial EEPROM, SOT-23-5; Manufacturer: Microchip; SymbolCreator: a0411947

## Sheet PGA309EVM_TEST_PCB_Project_EVM_Hardware.SchDoc
size 431 x 279 mm; Date: Not shown in title block; ApprovedBy: Not shown in title block; CheckedBy: Not shown in title block; Author: Not shown in title block; CompanyName: Not shown in title block; Engineer: Not shown in title block; Organization: Not shown in title block; Address1: Not shown in title block; Address2: Not shown in title block; Address3: Not shown in title block; Address4: Not shown in title block; DocumentNumber: 1; Revision: Use project parameter SCH_Rev; SheetNumber: 3; SheetTotal: 3; PageSetup: Record=PageOptions¦CenterHorizontal=True¦CenterVertical=True¦PrintScale=1.00¦XCorrection=1.00¦YCorrection=1.00¦PrintKind=0¦BorderSize=5000000¦LeftOffset=0¦BottomOffset=0¦Orientation=2¦PaperLength=1000¦PaperWidth=1000¦Scale=100¦PaperSource=15¦PrintQuality=600¦MediaType=1¦DitherType=10¦PaperKind=Letter¦PrintScaleMode=1
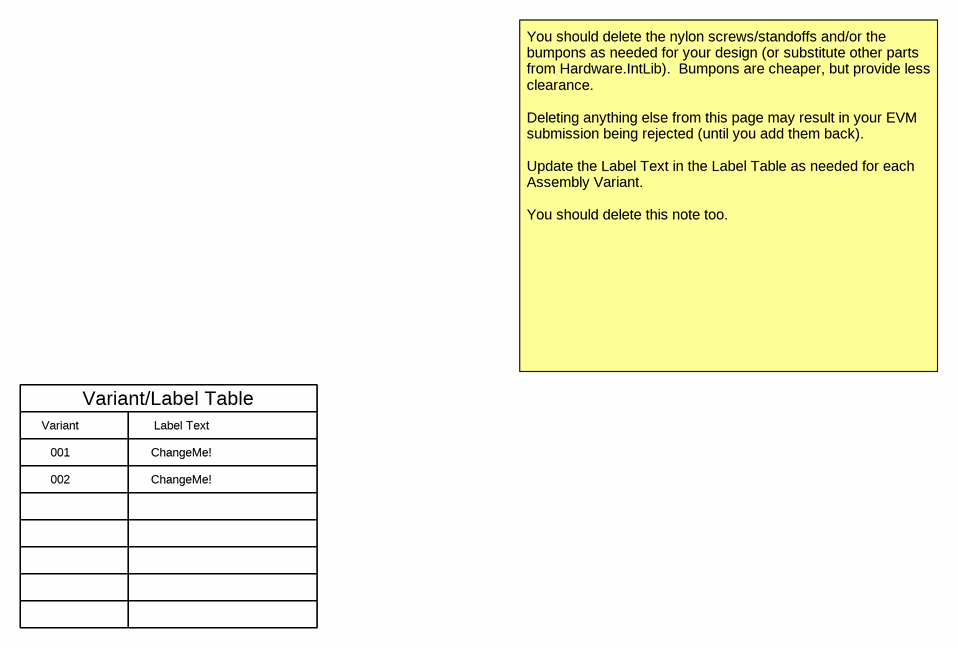
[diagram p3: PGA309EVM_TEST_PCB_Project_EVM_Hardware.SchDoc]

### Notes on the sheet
- Variant
- Variant/Label Table
- Label Text
- You should delete the nylon screws/standoffs and/or the bumpons as needed for your design (or substitute other parts from Hardware.IntLib).  Bumpons are cheaper, but provide less clearance.
  Deleting anything else from this page may result in your EVM submission being rejected (until you add them back).
  Update the Label Text in the Label Table as needed for each Assembly Variant.
  You should delete this note too.
- 001
- 002
- ChangeMe!

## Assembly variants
001: not fitted FID1 FID2 FID3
